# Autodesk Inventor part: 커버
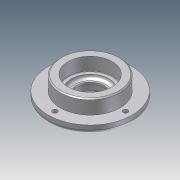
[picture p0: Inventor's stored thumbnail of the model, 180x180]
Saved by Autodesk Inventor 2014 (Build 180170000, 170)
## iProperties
Company: 한국ATC센터
Created: 2014-10
Part Number: 커버
Document SubType Name: Modeling
Designer: KYOUNG IL JANG
Density: 7.85 g/cm^3
Mass: 44.7286 g
Surface Area: 161.165 cm^2
Volume: 44.7286 cm^3
Material: 강철
Appearance: Steel
Author: KYOUNG IL JANG
Revision Number: 1
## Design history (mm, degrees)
sketch "스케치1"
  geometry: C1 r 38 at (0, 0); 1 further point
  constraints: 1 centre point, 1 coincident
  dimensions: "d0" = 76 diameter of C1
extrude "돌출1" new body sketch "스케치1" distance "d1" = 7; taper "d2" = 0 deg
sketch "스케치2"
  geometry: C1 r 27 at (0, 0); 1 further point
  constraints: 1 centre point, 1 coincident
  dimensions: "d3" = 54 diameter of C1
extrude "돌출2" join sketch "스케치2" distance "d4" = 13; taper "d5" = 0 deg
sketch "스케치3"
  geometry: C1 r 20 at (0, 0); 1 further point
  constraints: 1 centre point, 1 coincident
  dimensions: "d6" = 40 diameter of C1
extrude "돌출3" join sketch "스케치3" distance "d7" = 5; taper "d8" = 0 deg
hole "구멍1" diameter "d11" = 25; stored, may be unused: countersink angle "d15" = 90 deg, drill point angle "d17" = 118 deg; dims "d9" = 10, "d10" = 10, "d12" = 6, "d13" = 32, "d14" = 8.3, "d16" = 8
hole "구멍2" diameter "d20" = 34; stored, may be unused: countersink angle "d24" = 90 deg, drill point angle "d26" = 0 deg; dims "d18" = 10, "d19" = 10, "d21" = 6, "d22" = 40, "d23" = 12, "d25" = 3
fillet "모깎기2" dims "d34" = 3
fillet "모깎기1" dims "d27" = 0.3
chamfer "모따기1" distance "d28" = 1; stored, may be unused: second distance "d29" = 2, angle "d30" = 45 deg
chamfer "모따기2" distance "d31" = 1.2; stored, may be unused: second distance "d32" = 2, angle "d33" = 30 deg
sketch "스케치4" dims "d35" = 64
  geometry: 3 further points
  constraints: 2 horizontal alignment, 1 coincident, 2 other
hole "구멍3" sketch "스케치4" at (32, 0) diameter "d36" = 4.5; stored, may be unused: countersink angle "d40" = 90 deg, drill point angle "d42" = 118 deg; dims "d37" = 6, "d38" = 8, "d39" = 4.4, "d41" = 13
node "솔리드1"
pattern_circular "원형 패턴1" dims angle "d44" = 360 deg
